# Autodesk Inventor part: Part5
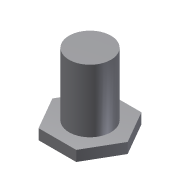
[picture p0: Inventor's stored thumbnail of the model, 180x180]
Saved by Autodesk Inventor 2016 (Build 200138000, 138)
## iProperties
Created: 2008-05
Part Number: Part5
Document SubType Name: Modeling
Designer: CADCIM
Density: 1 g/cm^3
Material: Generic
Appearance: Default
Author: CADCIM
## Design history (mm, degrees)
sketch "Sketch1"
  geometry: C1 r 2 at (-7.12, 11.618)
  constraints: 1 centre point
  dimensions: "d2" = 4 diameter of C1
extrude "Extrusion1" new body sketch "Sketch1" distance "d0" = 6; taper "d1" = 0 deg
sketch "Sketch2"
  geometry: L1 (-3.598, 0)-(-1.799, 3.116); L2 (-1.799, 3.116)-(1.799, 3.116); L3 (1.799, 3.116)-(3.598, 0); L4 (3.598, 0)-(1.799, -3.116); L5 (1.799, -3.116)-(-1.799, -3.116); L6 (-1.799, -3.116)-(-3.598, 0); C1 r 2 at (0, 0) reference; 1 further point
  constraints: 12 end point, 1 coincident, 13 other
extrude "Extrusion2" join sketch "Sketch2" distance "d3" = 1; taper "d4" = 0 deg
body "Solid1"
